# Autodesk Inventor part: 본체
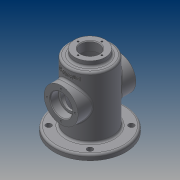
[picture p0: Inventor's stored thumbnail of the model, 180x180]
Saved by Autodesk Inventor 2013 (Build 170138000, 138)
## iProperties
Created: 2014-12
Part Number: 본체
Material: Generic
Document SubType Name: Modeling
Designer: CAD-B18
Density: 1 g/cm^3
Author: CAD-B18
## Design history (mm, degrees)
sketch "스케치1"
  geometry: C1 r 32.5 at (0, 0); 1 further point
  constraints: 1 centre point
  dimensions: "d1" = 65 diameter of C1
extrude "돌출1" new body sketch "스케치1" distance "d2" = 98; taper "d3" = 0 deg
fillet "모깎기1" dims "d4" = 3
feature "쉘1" dims "d5" = 5
fillet "모깎기2" dims "d6" = 3
sketch "스케치2"
  geometry: C1 r 52.5 at (0, 0); C2 r 27.5 at (0, 0) reference; 1 further point
  constraints: 1 centre point, 1 coincident
  dimensions: "d7" = 105 diameter of C1
extrude "돌출2" join sketch "스케치2" distance "d8" = 8; taper "d9" = 0 deg
fillet "모깎기3" dims "d10" = 3
node "작업 평면2"
sketch "스케치3"
  geometry: L1 (27.5, 0)-(-27.5, 0) reference; C1 r 25 at (0, 55); 1 further point
  constraints: 1 centre point, 1 vertical alignment
  dimensions: "d12" = 50 diameter of C1; "d13" = 55 distance from line of L1 C1.centre
extrude "돌출3" join sketch "스케치3" stored distance "d14" = 8; taper "d15" = 0 deg
hole "구멍1" diameter "d18" = 25; stored, may be unused: countersink angle "d22" = 90 deg, drill point angle "d24" = 118 deg; dims "d16" = 10, "d17" = 10, "d19" = 6, "d20" = 32, "d21" = 12, "d23" = 8
sketch "스케치4"
  geometry: C1 r 22.5 at (0, 0); 1 further point
  constraints: 1 centre point, 1 coincident
  dimensions: "d25" = 45 diameter of C1
extrude "돌출4" join sketch "스케치4" distance "d26" = 8; taper "d27" = 0 deg
fillet "모깎기4" dims "d28" = 3
hole "구멍2" diameter "d31" = 27; stored, may be unused: countersink angle "d35" = 90 deg, drill point angle "d37" = 118 deg; dims "d29" = 10, "d30" = 10, "d32" = 6, "d33" = 32, "d34" = 12, "d36" = 8
chamfer "모따기1" distance "d38" = 1; stored, may be unused: second distance "d39" = 2, angle "d40" = 45 deg
fillet "모깎기5" dims "d41" = 0.3
sketch "스케치5"
  geometry: L1 (52.5, -55)-(-52.5, -55) reference; 2 further points
  constraints: 1 vertical alignment
  dimensions: "d42" = 75.5 distance from line of L1 point (0, 20.5)
hole "구멍3" sketch "스케치5" at (0, 20.5) diameter "d43" = 2.459; stored, may be unused: countersink angle "d47" = 90 deg, drill point angle "d49" = 118 deg; dims "d44" = 6, "d45" = 32, "d46" = 12, "d48" = 8
sketch "스케치6"
  geometry: 2 further points
  constraints: 1 vertical alignment
  dimensions: "d53" = 17.5 distance of point (0, 0) point (0, 17.5)
hole "구멍4" sketch "스케치6" at (0, 17.5) diameter "d54" = 2.459; stored, may be unused: countersink angle "d58" = 90 deg, drill point angle "d60" = 118 deg; dims "d55" = 6, "d56" = 32, "d57" = 12, "d59" = 8
node "작업 평면3"
sketch "스케치7"
  geometry: L1 (-29.5, 98)-(29.5, 98) reference; 2 further points
  constraints: 1 vertical alignment, 1 other
  dimensions: "d64" = 9 distance from line of L1 point (0, 89)
feature "엠보싱1" sketch "스케치7" dims "d65" = 1, "d66" = 0
sketch "스케치8" dims "d67" = 86
  geometry: L1 (0, 0)-(68.728, -68.728); L2 (0, 0)-(97.196, 0); 2 further points
  constraints: 4 end point, 1 coincident, 1 equal length, 1 horizontal, 1 point on line, 3 other
  dimensions: "d68" = 45 deg angle of L1 L2
hole "구멍5" sketch "스케치8" at (30.406, -30.406) diameter "d69" = 8; stored, may be unused: countersink angle "d73" = 90 deg, drill point angle "d75" = 118 deg; dims "d70" = 6, "d71" = 32, "d72" = 12, "d74" = 8
node "솔리드1"
mirror "대칭1"
mirror "대칭2"
pattern_circular "원형 패턴1" dims angle "d51" = 360 deg
mirror "대칭3"
pattern_circular "원형 패턴2" dims angle "d62" = 360 deg
pattern_circular "원형 패턴3" dims angle "d77" = 360 deg
other parameters: "d11" = -42.5
